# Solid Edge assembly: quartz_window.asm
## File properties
Author: work
Template: Iso Assembly.asm
Last saved by: Lee
Revision: 69
Application: Solid Edge
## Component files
quartz_adapter.par
pmt.par
quartz_window.par
quartz_holder.par
quartz_window_sleeve.par
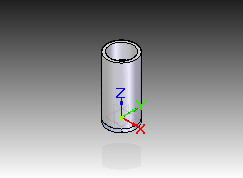
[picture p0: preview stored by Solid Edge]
